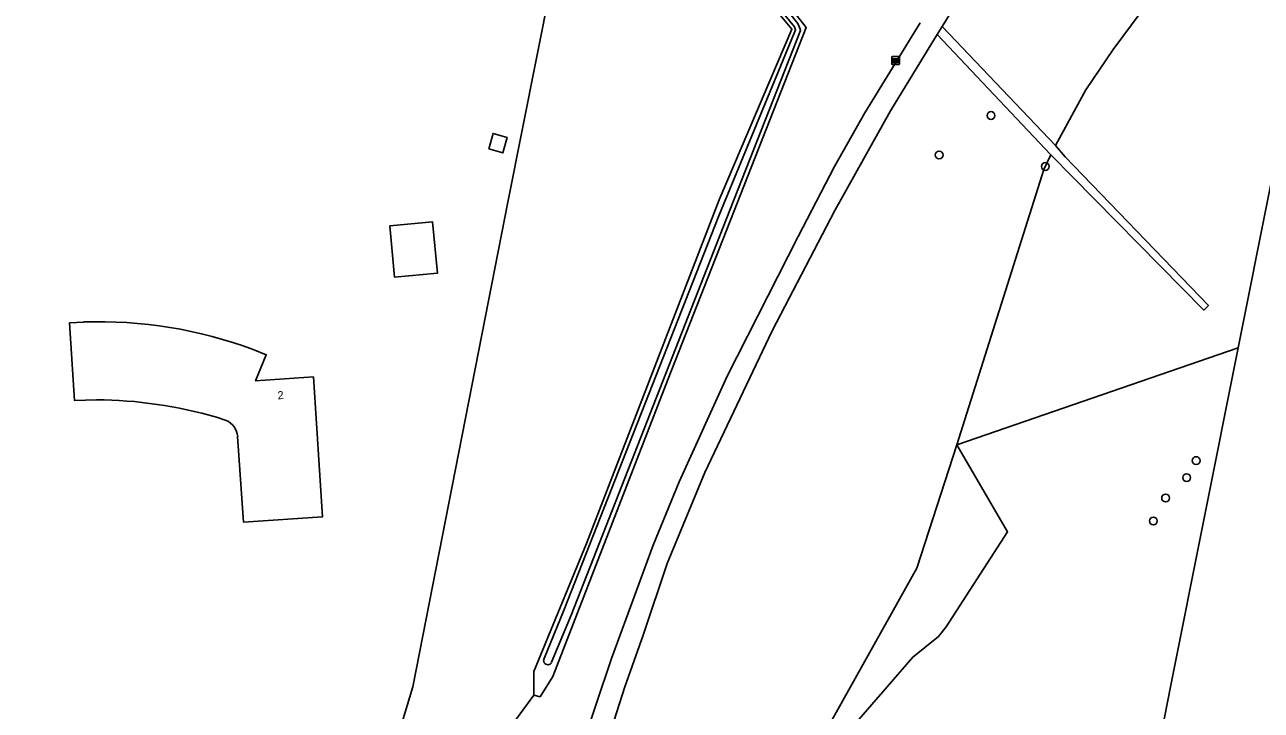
# Model space of a CAD drawing. Extents: x 162417 to 163721, y 384268 to 385416.
# Drawn here: x 162964 to 163118.6, y 385247.1 to 385332.8 of the extents above; entities that cross this region are included whole.
import ezdxf

# ---------------------------------------------------------------- set-up
doc = ezdxf.new("R2010")
doc.units = 0
for name, color, linetype in [('IMGEO_Boom', 7, 'Continuous'), ('IMGEO_Gemengd_bos', 7, 'Continuous'), ('IMGEO_Groenvoorziening', 7, 'Continuous'), ('IMGEO_Pand', 7, 'Continuous'), ('IMGEO_Pand_nummerreeks', 7, 'Continuous'), ('IMGEO_Voetpad_halfverhard', 7, 'Continuous'), ('IMGEO_Waterloop', 7, 'Continuous'), ('IMGEO_Wegwijzer', 7, 'Continuous')]:
    doc.layers.add(name, color=color, linetype=linetype)

msp = doc.modelspace()

# ---------------------------------------------------------------- linework, layer by layer
at = {"layer": 'IMGEO_Boom'}
for centre in [(163084.79, 385321.44), (163078.31, 385316.51), (163091.58, 385315.07), (163110.43, 385278.28), (163109.25, 385276.15), (163106.61, 385273.61), (163105.08, 385270.73)]:
    msp.add_circle(centre, 0.489, dxfattribs=at)
at = {"layer": 'IMGEO_Gemengd_bos'}
for points in [[(163129.12, 385354.44), (163103.55, 385334.4), (163100.06, 385329.69), (163096.66, 385324.65), (163092.84, 385317.68)], [(163171.61, 385317.19), (163154.66, 385322.14), (163125.26, 385340.42), (163123.47, 385331.45), (163115.67, 385292.37)], [(163092.28, 385316.53), (163091.39, 385314.7), (163080.54, 385280.24)], [(163080.54, 385280.24), (163115.67, 385292.37)], [(163115.67, 385292.37), (163107.22, 385250), (163103.3, 385229.91), (163087.26, 385230.97), (163087.35, 385230.19), (163089.09, 385214.58), (163090.71, 385200.08)], [(163060.59, 385237.05), (163062.04, 385240.39), (163064.85, 385245.75), (163067.23, 385250), (163075.52, 385264.83), (163080.54, 385280.24)], [(163080.54, 385280.24), (163086.86, 385269.38), (163079.19, 385257.47), (163078.22, 385256.3), (163075.02, 385253.7), (163071.81, 385250), (163060.59, 385237.05)]]:
    msp.add_lwpolyline(points, dxfattribs=at)
at = {"layer": 'IMGEO_Groenvoorziening'}
for points in [[(162983.1, 385215.85), (162999.67, 385223.85), (163002.31, 385228.02), (163005.52, 385233.58), (163009.66, 385241.99), (163011.19, 385245.56), (163012.52, 385250), (163024.43, 385310.81), (163029.79, 385337.67), (162986.75, 385346.16), (162983.96, 385346.72), (162964.03, 385350.65)], [(163027.67, 385248.94), (163028.43, 385248.75), (163030.01, 385251.27), (163044.45, 385288.5), (163061.68, 385332.47), (163047.67, 385350.42)], [(163046.16, 385348.81), (163059.91, 385332.22), (163050.83, 385310.9), (163034.23, 385267.93), (163027.67, 385251.91), (163027.67, 385248.94)], [(162993.26, 385185.69), (163019.63, 385237.96), (163027.67, 385248.94)]]:
    msp.add_lwpolyline(points, dxfattribs=at)
at = {"layer": 'IMGEO_Pand'}
for points in [[(163022.02, 385317.27), (163022.57, 385319.2), (163024.32, 385318.71), (163023.77, 385316.77), (163022.02, 385317.27)], [(163009.64, 385307.63), (163014.99, 385308.14), (163015.61, 385301.72), (163010.25, 385301.21), (163009.64, 385307.63)], [(162973, 385285.9), (162970.26, 385285.79), (162969.63, 385295.5), (162971.38, 385295.61)], [(162992.58, 385292.16), (162994.21, 385291.52), (162992.87, 385288.25), (163000.1, 385288.75)], [(163000.1, 385288.75), (163001.24, 385271.23), (162991.35, 385270.58), (162990.64, 385281.29)], [(162989.2, 385283.3), (162987.98, 385283.71)]]:
    msp.add_lwpolyline(points, dxfattribs=at)
for centre, radius, start, end in [((162973.31, 385240.62), 55.03, 69.4939, 92.0102), ((162972.48, 385229.92), 55.98, 73.9298, 89.464), ((162988.23, 385281.09), 2.42, 4.7975, 66.3693)]:
    msp.add_arc(centre, radius, start, end, dxfattribs=at)
at = {"layer": 'IMGEO_Voetpad_halfverhard'}
for points in [[(163120.56, 385378.46), (163108.97, 385366), (163097.9, 385353.97), (163087.24, 385342.4), (163079.77, 385334.32), (163078.68, 385332.56)], [(163031.15, 385233.91), (163033.48, 385241.98), (163037.34, 385253.52), (163042.57, 385267.72), (163045.81, 385275.63), (163051.83, 385288.85), (163060.69, 385306.29), (163065.22, 385315.05), (163069.02, 385321.76), (163075.92, 385333.04)], [(163078.68, 385332.56), (163078.07, 385331.58)], [(163078.07, 385331.58), (163077.87, 385331.26), (163072.21, 385322.02), (163065.28, 385309.54), (163057.46, 385294.51), (163049.04, 385276.79), (163044.33, 385265.41), (163041.33, 385256.44), (163039.04, 385250), (163034.13, 385234.62), (163028.7, 385216.13), (163026.7, 385207.75), (163023.08, 385191.41), (163022.21, 385186.4), (163021.45, 385178.97), (163021.25, 385172.03), (163021.25, 385170.51), (163021.25, 385166.4), (163021.75, 385163.91), (163024.55, 385156.22)]]:
    msp.add_lwpolyline(points, dxfattribs=at)
at = {"layer": 'IMGEO_Waterloop'}
for points in [[(163029.88, 385253.05), (163032.31, 385258.96), (163051.71, 385308.42), (163060.99, 385332.06), (163060.9, 385332.37), (163060.66, 385332.94), (163048.35, 385348.37), (163047.28, 385349.92), (163045.92, 385351.53), (163043.86, 385353.13), (163041.71, 385354.62), (163038.6, 385356.27), (163036, 385357.33), (163032.28, 385358.41), (162995.24, 385368.18), (162993.52, 385368.6), (162991.49, 385368.65), (162989.54, 385368.52), (162987.51, 385368.27), (162984.69, 385367.47), (162982.42, 385366.21), (162969.63, 385357.25)], [(163047.07, 385348.57), (163060.22, 385332.54), (163060.36, 385332.16), (163060.2, 385331.75), (163050.78, 385308.91), (163031.38, 385259.46), (163028.95, 385253.54)], [(163092.84, 385317.68), (163078.68, 385332.56)], [(163078.07, 385331.58), (163092.28, 385316.53)], [(163092.84, 385317.68), (163094.06, 385316.26), (163111.97, 385297.66), (163111.38, 385297.11), (163092.28, 385316.53)]]:
    msp.add_lwpolyline(points, dxfattribs=at)
msp.add_arc((163029.41, 385253.28), 0.527, 150.0028, 333.801, dxfattribs=at)
at = {"layer": 'IMGEO_Wegwijzer'}
for p, q in [((163072.38, 385327.92), (163072.38, 385328.71)), ((163072.38, 385328.71), (163072.38, 385327.92)), ((163072.48, 385328.81), (163073.27, 385328.81)), ((163073.27, 385328.81), (163072.48, 385328.81)), ((163073.27, 385327.82), (163072.48, 385327.82)), ((163072.48, 385327.82), (163073.27, 385327.82)), ((163073.37, 385328.71), (163073.37, 385327.92)), ((163073.37, 385327.92), (163073.37, 385328.71))]:
    msp.add_line(p, q, dxfattribs=at)
for points in [[(163072.48, 385328.55), (163073.27, 385328.55), (163073.27, 385328.08), (163072.48, 385328.08), (163072.48, 385328.55)], [(163072.55, 385328.4), (163072.55, 385328.32), (163072.55, 385328.23), (163072.96, 385328.23), (163072.96, 385328.15), (163073.21, 385328.32), (163072.96, 385328.48), (163072.96, 385328.4), (163072.55, 385328.4)]]:
    msp.add_lwpolyline(points, dxfattribs=at)
for centre, start, end in [((163072.48, 385328.71), 90, 180), ((163072.48, 385328.71), 90, 180), ((163072.48, 385327.92), 180, 270), ((163072.48, 385327.92), 180, 270), ((163073.27, 385328.71), 0, 90), ((163073.27, 385328.71), 360, 90), ((163073.27, 385327.92), 270, 0), ((163073.27, 385327.92), 270, 0)]:
    msp.add_arc(centre, 0.1, start, end, dxfattribs=at)

# ---------------------------------------------------------------- texts
at = {"layer": 'IMGEO_Pand_nummerreeks'}
msp.add_text('2', height=1, rotation=3.7185, dxfattribs=at).set_placement((162995.66, 385285.94))

doc.saveas('drawing.dxf')
